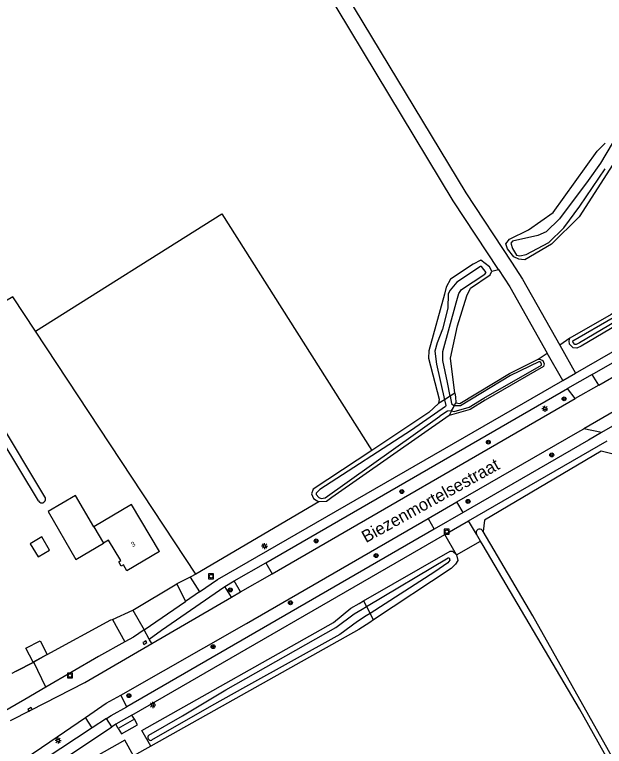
# Model space of a CAD drawing. Extents: x 137000 to 140001, y 403500 to 406000.
# Drawn here: x 139573.5 to 139693.7, y 403918.5 to 404067.6 of the extents above; entities that cross this region are included whole.
import ezdxf

# ---------------------------------------------------------------- set-up
doc = ezdxf.new("R2010")
doc.units = 0
for name, color, linetype in [('gg-afsc-draadraster', 7, 'Continuous'), ('gg-afsc-erfafscheiding', 7, 'Continuous'), ('gg-afsc-hekwerk', 7, 'Continuous'), ('gg-anno-huisnummerreeks BGT', 7, 'Continuous'), ('gg-anno-openbare ruimte label', 7, 'Continuous'), ('gg-bbg-abri', 7, 'Continuous'), ('gg-bbg-bijgebouw', 7, 'Continuous'), ('gg-bbg-gedigitaliseerde bijgebouw', 7, 'Continuous'), ('gg-bbg-hoofdgebouw', 7, 'Continuous'), ('gg-bbg-luifel en loopbrug', 7, 'Continuous'), ('gg-bbg-tussenscheiding', 7, 'Continuous'), ('gg-knt-bronhoudergrens', 7, 'Continuous'), ('gg-knt-onverhard', 7, 'Continuous'), ('gg-knt-verharding', 7, 'Continuous'), ('gg-knt-verharding nz', 7, 'Continuous'), ('gg-kntw-bovenkant insteek waterloop', 7, 'Continuous'), ('gg-kntw-waterlijn', 7, 'Continuous'), ('gt-grn-groengrens', 7, 'Continuous'), ('gt-grn-groengrens NZ', 7, 'Continuous'), ('gt-grn-vlakafsluiter', 7, 'Continuous'), ('gt-grn-weggrens', 7, 'Continuous'), ('gt-symb-boom', 7, 'Continuous'), ('gt-symb-kolk', 7, 'Continuous'), ('gt-symb-lichtmast', 7, 'Continuous'), ('gt-symb-rioolschacht', 7, 'Continuous')]:
    doc.layers.add(name, color=color, linetype=linetype)

# ---------------------------------------------------------------- blocks, each defined once
blk = doc.blocks.new('gt0-LMAST')
at = {"layer": 'gt-symb-lichtmast'}
for p, q in [((-0.18, 0.17), (-0.45, 0.44)), ((-0.01, 0.25), (-0.01, 0.62)), ((0.17, 0.17), (0.44, 0.44)), ((-0.26, 0), (-0.63, 0)), ((-0.18, -0.18), (-0.45, -0.45)), ((-0.01, -0.25), (-0.01, -0.63)), ((0.44, -0.45), (0.17, -0.18)), ((0.24, 0), (0.62, 0))]:
    blk.add_line(p, q, dxfattribs=at)
blk.add_circle((-0.01, 0), 0.25, dxfattribs=at)
blk = doc.blocks.new('gt0-BOOM')
at = {"layer": 'gt-symb-boom'}
for radius in [0.4, 0.2]:
    blk.add_circle((0, 0), radius, dxfattribs=at)
blk = doc.blocks.new('gt0-RS')
at = {"layer": 'gt-symb-rioolschacht'}
blk.add_lwpolyline([(-0.5, -0.5), (0.5, -0.5), (0.5, 0.5), (-0.5, 0.5)], close=True, dxfattribs=at)
blk.add_circle((0, 0), 0.375, dxfattribs=at)
blk = doc.blocks.new('gt0-KOLK')
at = {"layer": 'gt-symb-kolk'}
blk.add_lwpolyline([(0, 0), (0.37, 0), (0.37, 0.4), (-0.38, 0.4), (-0.38, 0), (0, 0)], dxfattribs=at)

msp = doc.modelspace()

# ---------------------------------------------------------------- linework, layer by layer
at = {"layer": 'gg-afsc-draadraster'}
msp.add_line((139610.44, 403953.61), (139577.76, 404003.1), dxfattribs=at)
msp.add_lwpolyline([(139577.76, 404003.1), (139573.16, 404010.07), (139523.72, 403980.95)], dxfattribs=at)
at = {"layer": 'gg-afsc-erfafscheiding'}
for p, q in [((139610.44, 403953.61), (139609.29, 403952.94)), ((139597.6, 403946.27), (139606.59, 403951.64)), ((139580.18, 403937.2), (139577.44, 403935.66)), ((139577.44, 403935.66), (139573.85, 403933.81)), ((139573.85, 403933.81), (139572.98, 403933.36))]:
    msp.add_line(p, q, dxfattribs=at)
at = {"layer": 'gg-afsc-hekwerk'}
for p, q in [((139580.18, 403937.2), (139593.14, 403944.25)), ((139573.85, 403933.81), (139577.44, 403935.66))]:
    msp.add_line(p, q, dxfattribs=at)
at = {"layer": 'gg-bbg-abri'}
for p, q in [((139597.91, 403924.03), (139594.63, 403922.17)), ((139598.56, 403922.9), (139597.91, 403924.03))]:
    msp.add_line(p, q, dxfattribs=at)
msp.add_lwpolyline([(139594.63, 403922.17), (139595.28, 403921.04), (139598.56, 403922.9)], dxfattribs=at)
at = {"layer": 'gg-bbg-bijgebouw'}
msp.add_lwpolyline([(139589.64, 403963.24), (139585.92, 403969.58), (139580.33, 403966.31), (139586.02, 403956.59), (139591.61, 403959.87)], dxfattribs=at)
at = {"layer": 'gg-bbg-gedigitaliseerde bijgebouw'}
msp.add_lwpolyline([(139580.18, 403937.2), (139577.3, 403935.68), (139575.82, 403938.47), (139578.7, 403940), (139580.18, 403937.2)], dxfattribs=at)
at = {"layer": 'gg-bbg-hoofdgebouw'}
for points in [[(139603.01, 403958.21), (139597.32, 403967.8), (139589.64, 403963.24)], [(139603.01, 403958.21), (139596.4, 403954.28), (139595.68, 403955.48), (139595.26, 403955.23), (139594.76, 403956.08), (139595.17, 403956.33), (139592.67, 403960.5), (139591.61, 403959.87)]]:
    msp.add_lwpolyline(points, dxfattribs=at)
at = {"layer": 'gg-bbg-luifel en loopbrug'}
msp.add_lwpolyline([(139580.64, 403958.48), (139579.06, 403961.17), (139576.71, 403959.78), (139578.29, 403957.1), (139580.64, 403958.48)], dxfattribs=at)
at = {"layer": 'gg-bbg-tussenscheiding'}
msp.add_line((139589.64, 403963.24), (139591.61, 403959.87), dxfattribs=at)
at = {"layer": 'gg-knt-bronhoudergrens'}
msp.add_line((139601.24, 403918.51), (139597.76, 403916.55), dxfattribs=at)
msp.add_lwpolyline([(139696.04, 403977.87), (139693.05, 403978.6), (139669.28, 403964.55), (139669, 403962.25)], dxfattribs=at)
at = {"layer": 'gg-knt-onverhard'}
for p, q in [((139684.57, 404000.24), (139687.78, 403994.55)), ((139685.18, 403993.05), (139682.05, 403998.59)), ((139685.18, 403993.05), (139687.78, 403994.55)), ((139667.61, 403961.7), (139666.02, 403964.46)), ((139663.56, 403957.5), (139661.17, 403961.66))]:
    msp.add_line(p, q, dxfattribs=at)
for points in [[(139491.29, 404029.87), (139494.97, 404032.89), (139503.02, 404040.36), (139510.26, 404050.58), (139527.49, 404081.69), (139540.58, 404106.68), (139553.04, 404125.36), (139568.03, 404138.11), (139589.58, 404152.78), (139603.6, 404158.75), (139631.51, 404167.9), (139632.52, 404165.07), (139604.66, 404155.94), (139589.5, 404149.48), (139589.47, 404144.47), (139591.17, 404139.97), (139612.78, 404114.78), (139639.17, 404074.78), (139665.44, 404031.24), (139674.74, 404017.1), (139677, 404013.66), (139684.57, 404000.24)], [(139672.1, 404015.65), (139662.9, 404029.64), (139636.63, 404073.18), (139610.38, 404112.97), (139588.9, 404138.01), (139584.48, 404139.45), (139577.11, 404140.66), (139569.85, 404135.72), (139555.3, 404123.34), (139543.16, 404105.15), (139530.13, 404080.27), (139512.8, 404048.98), (139505.28, 404038.37), (139496.94, 404030.62), (139492.61, 404027.08)], [(139672.1, 404015.65), (139674.44, 404012.1), (139682.05, 403998.59)]]:
    msp.add_lwpolyline(points, dxfattribs=at)
at = {"layer": 'gg-knt-verharding'}
for p, q in [((139687.78, 403994.55), (139799.77, 404059.14)), ((139691.18, 403994.25), (139769.04, 404039.17)), ((139692.54, 403992.1), (139770.37, 404037.02)), ((139691.18, 403994.25), (139686.18, 403991.37)), ((139692.54, 403992.1), (139691.18, 403994.25)), ((139624.68, 403955.89), (139686.18, 403991.37)), ((139687.74, 403989.33), (139686.18, 403991.37)), ((139625.96, 403953.67), (139687.74, 403989.33)), ((139697.85, 403985.16), (139693.12, 403982.42)), ((139693.12, 403982.42), (139689.49, 403983.2)), ((139666.02, 403964.46), (139694.23, 403980.73)), ((139657.77, 403964.9), (139663.64, 403968.28)), ((139664.89, 403966.12), (139663.64, 403968.28)), ((139657.77, 403964.9), (139659.02, 403962.73)), ((139664.89, 403966.12), (139659.02, 403962.73)), ((139661.17, 403961.66), (139666.02, 403964.46)), ((139659.02, 403962.73), (139596.4, 403926.57)), ((139597.43, 403924.88), (139661.17, 403961.66)), ((139618.27, 403952.19), (139624.68, 403955.89)), ((139624.68, 403955.89), (139625.96, 403953.67)), ((139609.29, 403952.94), (139606.59, 403951.64)), ((139609.29, 403952.94), (139611.21, 403949.96)), ((139619.55, 403949.97), (139625.96, 403953.67)), ((139606.59, 403951.64), (139608.35, 403948.01)), ((139616.35, 403951.08), (139618.27, 403952.19)), ((139619.55, 403949.97), (139618.27, 403952.19)), ((139611.21, 403949.96), (139608.35, 403948.01)), ((139617.68, 403948.89), (139619.55, 403949.97)), ((139601.46, 403939.44), (139617.68, 403948.89)), ((139599.92, 403942.24), (139608.35, 403948.01)), ((139593.48, 403944.36), (139597.6, 403946.27)), ((139597.6, 403946.27), (139599.92, 403942.24)), ((139580.18, 403937.2), (139593.14, 403944.25)), ((139593.14, 403944.25), (139593.48, 403944.36)), ((139593.48, 403944.36), (139595.99, 403939.78)), ((139601.46, 403939.44), (139600.95, 403940.31)), ((139579.88, 403930.54), (139577.44, 403935.66)), ((139596.4, 403926.57), (139595.14, 403928.96)), ((139597.43, 403924.88), (139594.17, 403923)), ((139589.33, 403922.26), (139587.97, 403924.39)), ((139592.23, 403924.17), (139589.33, 403922.26)), ((139573.1, 403909.05), (139593.34, 403922.49))]:
    msp.add_line(p, q, dxfattribs=at)
for points in [[(139611.21, 403949.96), (139614.87, 403952.47), (139685.18, 403993.05)], [(139663.64, 403968.28), (139688.26, 403982.49), (139689.49, 403983.2)], [(139693.12, 403982.42), (139690.46, 403980.89), (139664.89, 403966.12)], [(139595.14, 403928.96), (139620.76, 403943.55), (139657.77, 403964.9)], [(139600.95, 403940.31), (139603.45, 403942.18), (139616.35, 403951.08)], [(139599.92, 403942.24), (139597.77, 403940.77), (139595.99, 403939.78)], [(139595.99, 403939.78), (139590.62, 403936.79), (139579.88, 403930.54)], [(139572.65, 403923.79), (139576.85, 403925.9), (139587.84, 403931.5), (139601.46, 403939.44)], [(139579.88, 403930.54), (139575.57, 403928.04), (139565.89, 403922.48), (139565.01, 403922.05)], [(139592.23, 403924.17), (139593.19, 403924.82), (139596.4, 403926.57)], [(139573.88, 403914.8), (139575.41, 403915.81), (139580.71, 403919.42), (139587.97, 403924.39)], [(139589.33, 403922.26), (139576.58, 403913.87), (139575.17, 403912.92)], [(139594.17, 403923), (139593.67, 403922.71), (139593.34, 403922.49)]]:
    msp.add_lwpolyline(points, dxfattribs=at)
at = {"layer": 'gg-knt-verharding nz'}
for p, q in [((139692.54, 403992.1), (139687.74, 403989.33)), ((139697.89, 403988.04), (139689.49, 403983.2))]:
    msp.add_line(p, q, dxfattribs=at)
msp.add_lwpolyline([(139587.97, 403924.39), (139592.2, 403927.29), (139595.14, 403928.96)], dxfattribs=at)
at = {"layer": 'gg-kntw-bovenkant insteek waterloop'}
for p, q in [((139669, 403962.25), (139668.85, 403962.5)), ((139668.43, 403960.33), (139667.61, 403961.7)), ((139668.95, 403959.45), (139668.43, 403960.33)), ((139663.56, 403957.5), (139663.8, 403956.39)), ((139643.72, 403947.62), (139644.59, 403948.12)), ((139646.67, 403944.28), (139645.86, 403943.74))]:
    msp.add_line(p, q, dxfattribs=at)
for points in [[(139761.95, 404046.65), (139762.78, 404046.85), (139763.71, 404046.84), (139764.16, 404046.59), (139764.56, 404046.21), (139764.52, 404045.67), (139764.08, 404045.15), (139763.7, 404044.87), (139739.88, 404030.2), (139722.63, 404019.63), (139703.92, 404008.87), (139688.96, 404000.03), (139688.07, 403999.59), (139687.32, 403999.66), (139686.58, 404000.42), (139686.47, 404001.1), (139686.67, 404001.62)], [(139761.95, 404046.65), (139738.9, 404033.29), (139708.46, 404014.76), (139695.07, 404006.48), (139686.67, 404001.62)], [(139696.61, 404038.95), (139688.52, 404026.4), (139682.9, 404020.8), (139677.48, 404017.61), (139676.82, 404017.67), (139676.26, 404017.73), (139675.21, 404018.2), (139673.95, 404019.84), (139673.6, 404020.86), (139674.34, 404021.84), (139678.25, 404023.7), (139683.22, 404027.23), (139692.2, 404039.73), (139693.87, 404041.36)], [(139670.73, 404015.29), (139670.25, 404016.19), (139668.49, 404017.53), (139666.96, 404016.76), (139662.3, 404013.66), (139661.45, 404012.05), (139661.1, 404010.61), (139657.9, 403999.04), (139657.82, 403997.59), (139660.01, 403989.25), (139659.87, 403988.33)], [(139663.22, 403990.42), (139662.3, 403997.6), (139663.75, 404004.14), (139665.65, 404010.28), (139666.4, 404011.85), (139670.39, 404014.57), (139670.73, 404015.29)], [(139579.69, 403969.33), (139560.14, 404001.85), (139547.64, 403994.32)], [(139578.38, 403968.51), (139559.51, 403999.74), (139548.3, 403993.09)], [(139680.2, 403997.38), (139680.68, 403997.33), (139681.14, 403997.07), (139681.42, 403996.39), (139681.26, 403995.85), (139669.41, 403988.99), (139666.31, 403987.12), (139662.04, 403985.89)], [(139663.43, 403988.48), (139664.25, 403988.37), (139674.32, 403994.47), (139680.2, 403997.38)], [(139663.22, 403990.42), (139663.32, 403989.67), (139663.43, 403988.48)], [(139659.87, 403988.33), (139657.91, 403986.48), (139646.3, 403978.79)], [(139662.04, 403985.89), (139638.16, 403969.17), (139637.06, 403968.36), (139635.51, 403968.29)], [(139646.3, 403978.79), (139634.36, 403970.88), (139634.01, 403969.96), (139634.43, 403968.99), (139635.51, 403968.29)], [(139735.5, 403845.43), (139717.23, 403876.92), (139698.54, 403910.55), (139679.07, 403945.07), (139669, 403962.25)], [(139632.72, 403808.27), (139679.07, 403834.33), (139725.39, 403860.67), (139705.46, 403896.06), (139688.62, 403926.14), (139668.95, 403959.45)], [(139644.59, 403948.12), (139662.26, 403958.25), (139662.76, 403958.26), (139663.56, 403957.5)], [(139663.8, 403956.39), (139663.32, 403955.64), (139662.48, 403954.75), (139646.67, 403944.28)], [(139601.24, 403918.51), (139599.43, 403921.74), (139638.46, 403943.76), (139642.02, 403946.65), (139643.72, 403947.62)], [(139645.86, 403943.74), (139643.68, 403942.3), (139601.24, 403918.51)], [(139597.76, 403916.55), (139595.95, 403919.77), (139582.26, 403912.05), (139582.08, 403911.85)]]:
    msp.add_lwpolyline(points, dxfattribs=at)
for centre, radius, start, end in [((139579.06, 403968.88), 0.774, 208.1159, 35.8084), ((139668.27, 403962.04), 0.739, 38.7647, 207.1459)]:
    msp.add_arc(centre, radius, start, end, dxfattribs=at)
at = {"layer": 'gg-kntw-waterlijn'}
for p, q in [((139644.36, 403946.46), (139645.22, 403946.97)), ((139645.96, 403945.59), (139645.13, 403945.06))]:
    msp.add_line(p, q, dxfattribs=at)
for points in [[(139762.75, 404045.16), (139739.49, 404030.84), (139722.25, 404020.27), (139703.54, 404009.52), (139688.6, 404000.69), (139687.93, 404000.36), (139687.66, 404000.38), (139687.29, 404000.77), (139687.24, 404001.02), (139687.27, 404001.1), (139695.45, 404005.83), (139708.85, 404014.12), (139739.29, 404032.64), (139762.23, 404045.94)], [(139695.29, 404041.28), (139692.89, 404037.32), (139690.4, 404033.79), (139684.52, 404025.99), (139681.81, 404023.29), (139680.12, 404022.56), (139674.99, 404021.41), (139674.65, 404021.02), (139674.94, 404019.93), (139675.77, 404018.59), (139676.43, 404018.39), (139677.76, 404018.7), (139682.34, 404021.14), (139685.42, 404024.13), (139688.65, 404028.57), (139693.87, 404036.18)], [(139662.27, 403989.83), (139661.72, 403992.64), (139660.73, 403997.07), (139660.79, 403998.95), (139663.5, 404008.87), (139663.99, 404010.78), (139664.59, 404011.56), (139669.29, 404014.69), (139669.59, 404015.05), (139668.62, 404016.25), (139668.42, 404016.26), (139663.59, 404013.06), (139662.28, 404011.46), (139661.88, 404010.68), (139661.8, 404007.74), (139660.69, 404003.47), (139659.63, 404000.68), (139659.14, 403998.97), (139659.5, 403996.33), (139661.1, 403989.1)], [(139662.55, 403986.84), (139663.04, 403986.7), (139666.11, 403987.58), (139669.15, 403989.42), (139680.84, 403996.18), (139680.89, 403996.36), (139680.74, 403996.72), (139680.52, 403996.84), (139680.29, 403996.86), (139674.56, 403994.03), (139664.36, 403987.85), (139663.1, 403987.85)], [(139661.1, 403989.1), (139661.36, 403987.92), (139661.29, 403987.73), (139654.37, 403982.94), (139635.69, 403970.83), (139634.99, 403970.09), (139634.95, 403969.79), (139635.5, 403969.22), (139636, 403968.98), (139636.82, 403969.14), (139660.18, 403985.73)], [(139662.27, 403989.83), (139662.55, 403988.37), (139663.1, 403987.85)], [(139662.55, 403986.84), (139661.73, 403986.77), (139660.18, 403985.73)], [(139645.22, 403946.97), (139661.84, 403956.93), (139662.03, 403956.93), (139662.16, 403956.42), (139661.78, 403955.9), (139659.14, 403954.04), (139645.96, 403945.59)], [(139600.87, 403920.8), (139607.71, 403924.71), (139616.56, 403930.01), (139638.98, 403942.7), (139642.71, 403945.47), (139644.36, 403946.46)], [(139645.13, 403945.06), (139643.36, 403943.92), (139639.75, 403941.28), (139620.56, 403930.65), (139613.62, 403926.74), (139601.44, 403919.74)]]:
    msp.add_lwpolyline(points, dxfattribs=at)
msp.add_arc((139601.28, 403920.34), 0.618, 132.0628, 285.4545, dxfattribs=at)
at = {"layer": 'gt-grn-groengrens'}
for p, q in [((139670.73, 404015.29), (139672.1, 404015.65)), ((139686.67, 404001.62), (139684.57, 404000.24)), ((139680.2, 403997.38), (139682.05, 403998.59))]:
    msp.add_line(p, q, dxfattribs=at)
msp.add_lwpolyline([(139577.76, 404003.1), (139615.74, 404026.96), (139646.3, 403978.79)], dxfattribs=at)
at = {"layer": 'gt-grn-groengrens NZ'}
msp.add_line((139635.51, 403968.29), (139610.44, 403953.61), dxfattribs=at)
at = {"layer": 'gt-grn-vlakafsluiter'}
for p, q in [((139663.22, 403990.42), (139662.27, 403989.83)), ((139661.1, 403989.1), (139659.87, 403988.33)), ((139662.27, 403989.83), (139661.1, 403989.1)), ((139663.1, 403987.85), (139663.43, 403988.48)), ((139662.55, 403986.84), (139662.04, 403985.89)), ((139663.56, 403957.5), (139668.43, 403960.33)), ((139644.59, 403948.12), (139645.22, 403946.97)), ((139645.22, 403946.97), (139645.96, 403945.59)), ((139646.67, 403944.28), (139645.96, 403945.59))]:
    msp.add_line(p, q, dxfattribs=at)
msp.add_lwpolyline([(139662.55, 403986.84), (139662.94, 403987.56), (139663.1, 403987.85)], dxfattribs=at)
at = {"layer": 'gt-grn-weggrens'}
for p, q in [((139617.68, 403948.89), (139616.35, 403951.08)), ((139600.95, 403940.31), (139599.92, 403942.24)), ((139597.91, 403924.03), (139597.43, 403924.88)), ((139593.34, 403922.49), (139592.23, 403924.17)), ((139594.63, 403922.17), (139594.17, 403923))]:
    msp.add_line(p, q, dxfattribs=at)

# ---------------------------------------------------------------- block references
at = {"layer": 'gt-symb-boom'}
for p in [(139685.47, 403989.29), (139670.04, 403980.47), (139682.95, 403977.87), (139652.41, 403970.4), (139665.9, 403968.4), (139634.96, 403960.35), (139647.17, 403957.36), (139617.46, 403950.38), (139629.71, 403947.76), (139613.96, 403938.81), (139596.8, 403928.82)]:
    msp.add_blockref('gt0-BOOM', p, dxfattribs=at)
at = {"layer": 'gt-symb-kolk'}
for p, rotation in [((139599.95, 403939.81), -150.119987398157), ((139576.76, 403925.86), 27.185767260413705)]:
    msp.add_blockref('gt0-KOLK', p, dxfattribs=dict(at, rotation=rotation))
at = {"layer": 'gt-symb-lichtmast'}
for p in [(139681.56, 403987.28), (139624.44, 403959.29), (139601.67, 403926.93), (139582.39, 403919.7)]:
    msp.add_blockref('gt0-LMAST', p, dxfattribs=at)
at = {"layer": 'gt-symb-rioolschacht'}
for p in [(139661.56, 403962.23), (139613.55, 403953.15), (139584.8, 403932.93)]:
    msp.add_blockref('gt0-RS', p, dxfattribs=at)

# ---------------------------------------------------------------- texts
at = {"layer": 'gg-anno-huisnummerreeks BGT'}
msp.add_text('3', height=1, rotation=30.7, dxfattribs=at).set_placement((139597.58, 403959.06))
at = {"layer": 'gg-anno-openbare ruimte label'}
msp.add_text('Biezenmortelsestraat', height=2.5, rotation=29, dxfattribs=at).set_placement((139645.1, 403959.89))

doc.saveas('drawing.dxf')
